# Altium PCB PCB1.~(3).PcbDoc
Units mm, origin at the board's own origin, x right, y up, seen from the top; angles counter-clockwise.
Board outline 127 x 101.6 mm, 3 copper layers (Top Layer, Internal Plane 1, Bottom Layer); 15 components, 13 nets, 51 pads, 0 vias.
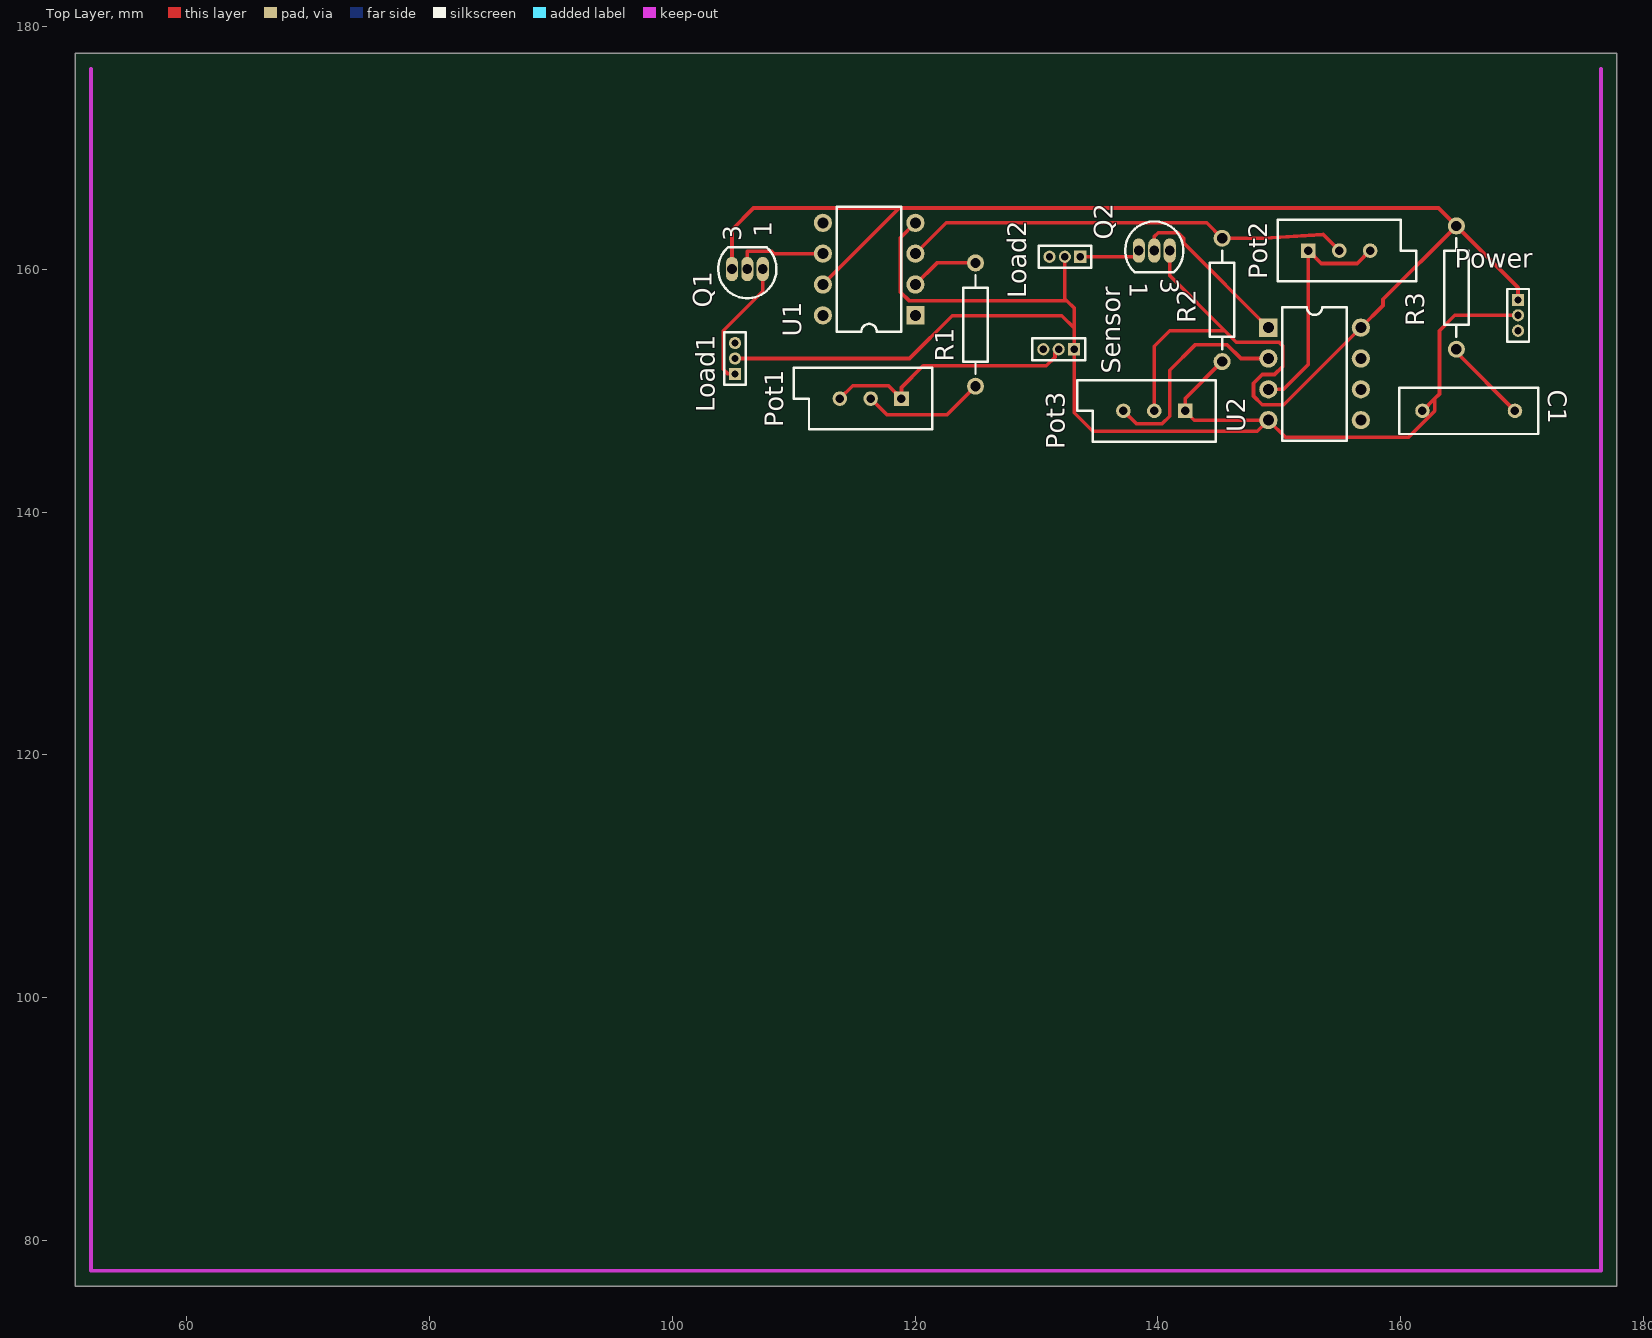
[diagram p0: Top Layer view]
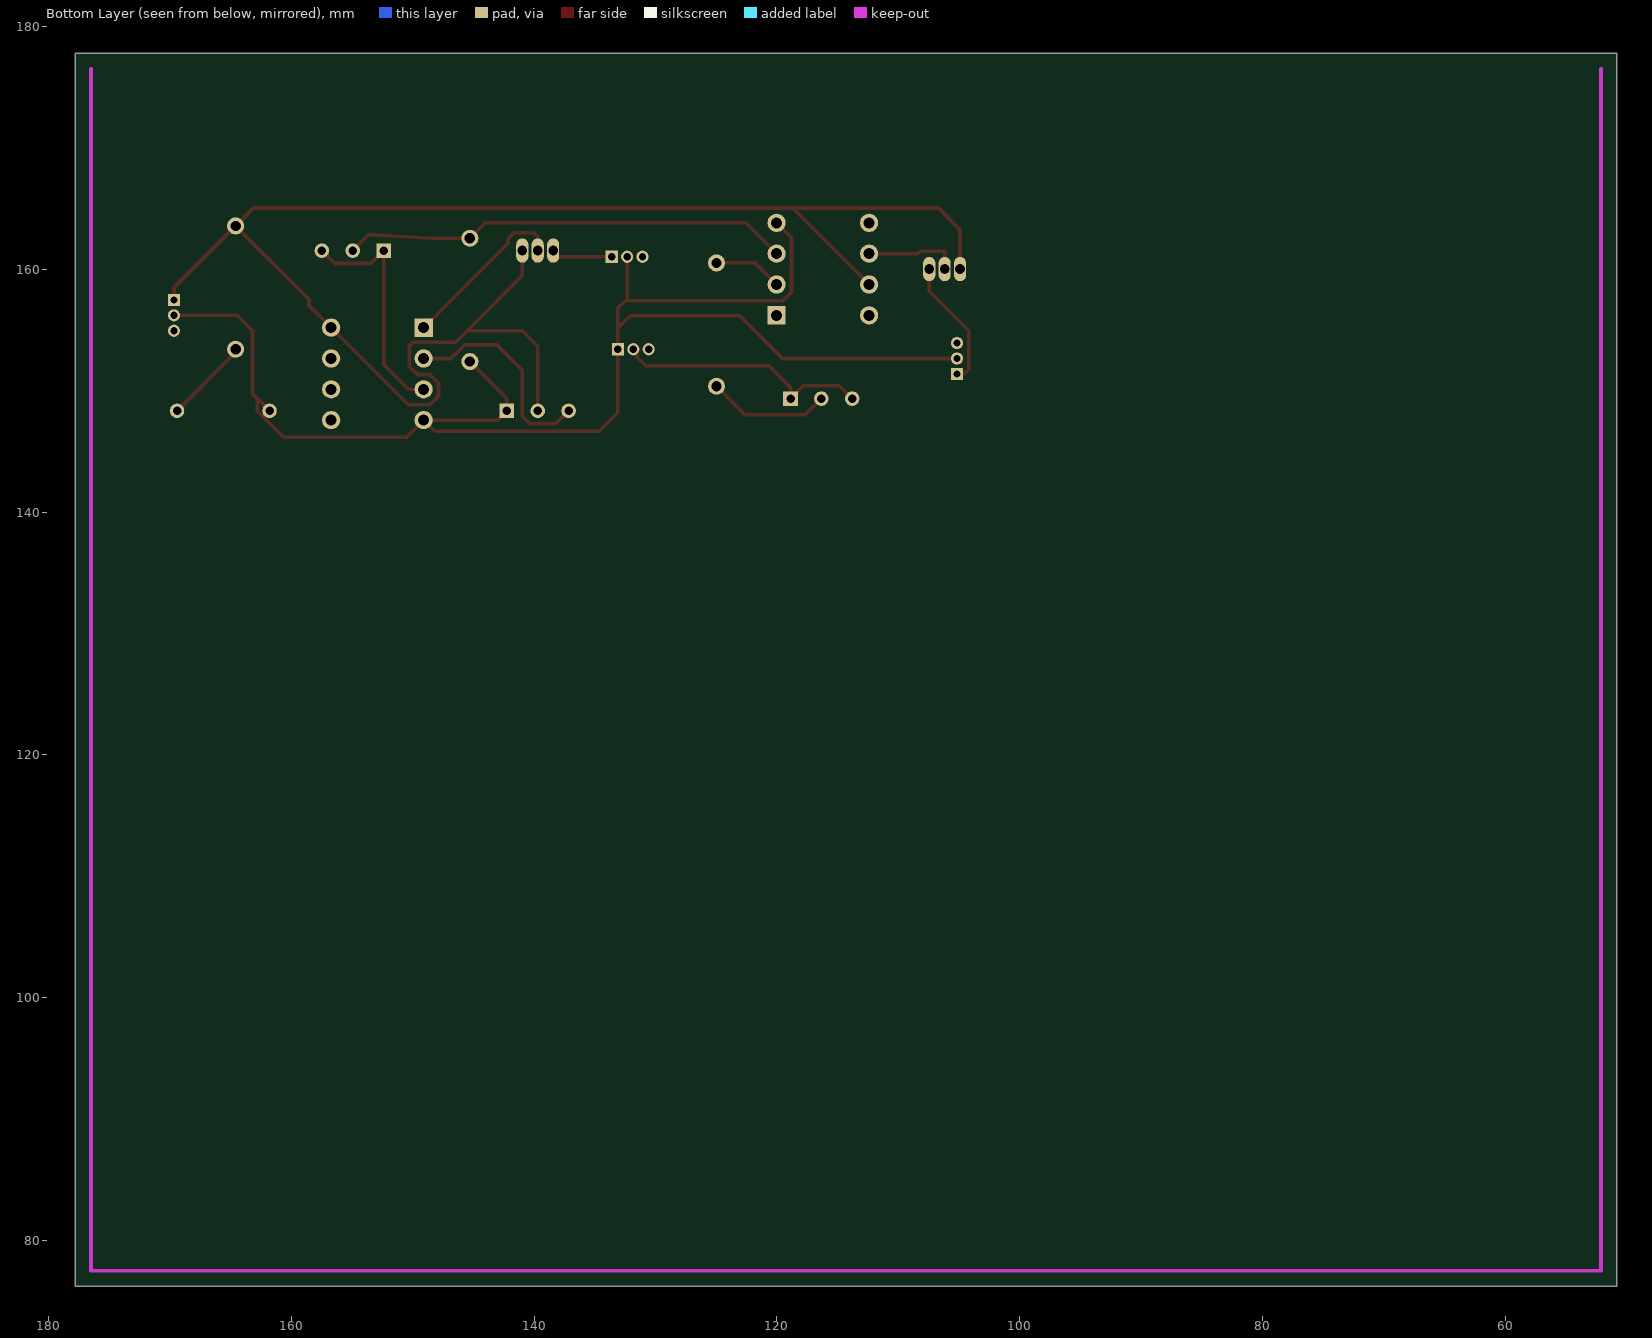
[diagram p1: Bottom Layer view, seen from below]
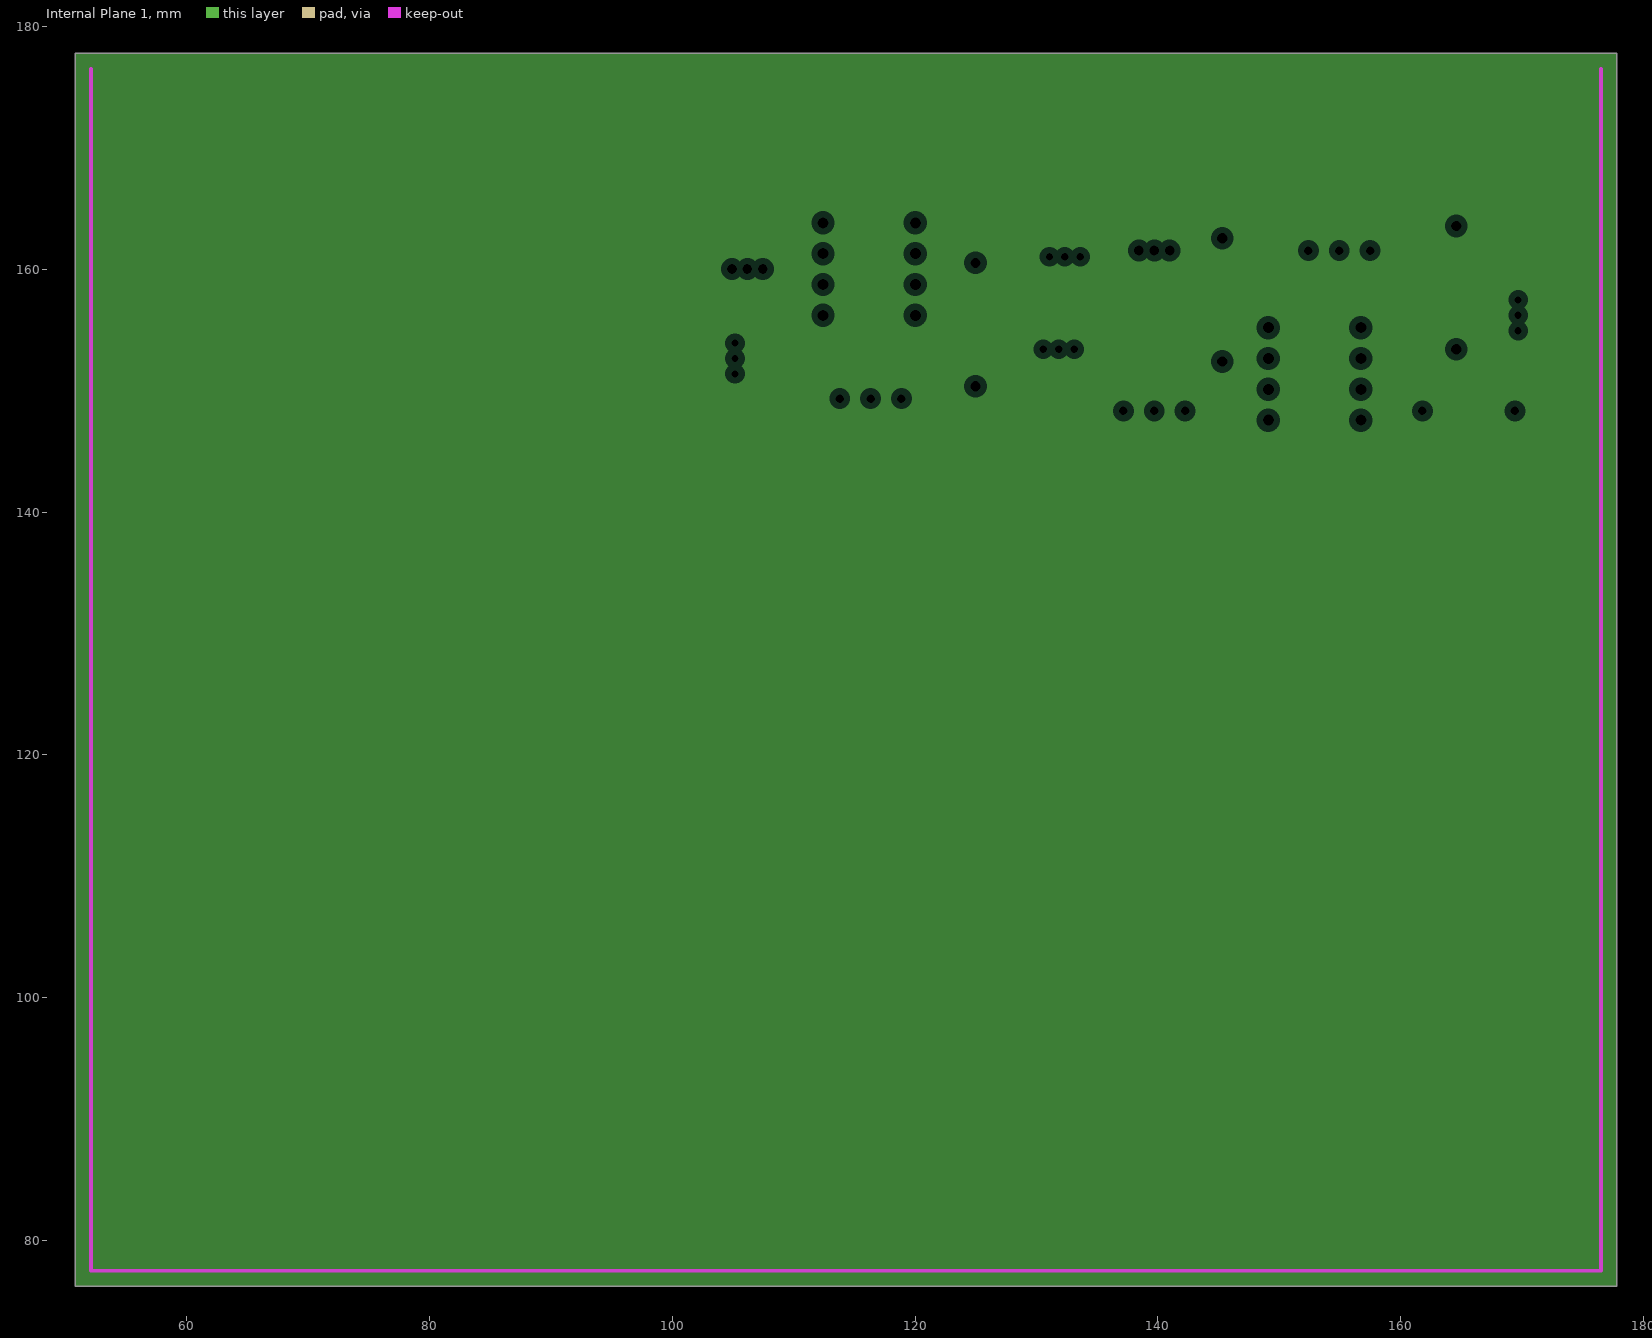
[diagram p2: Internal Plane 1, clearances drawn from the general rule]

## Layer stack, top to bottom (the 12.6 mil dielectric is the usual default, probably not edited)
Top Layer: signal copper 0.0356
Dielectric: dielectric 0.32, FR-4, Dk 4.8
Internal Plane 1: plane copper 0.0356
Dielectric: dielectric 0.32, FR-4, Dk 4.8
Bottom Layer: signal copper 0.0356

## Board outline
50.8,76.2 177.8,76.2 177.8,177.8 50.8,177.8

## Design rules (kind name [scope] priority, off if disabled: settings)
Clearance [All] p1: gap=0.3
ComponentClearance [All] p1: gap=0.254 collisioncheckmode=3 verticalgap=0.254
PlaneClearance [All] p1: clearance=0.508
PlaneConnect [All] p1: planeconnectstyle=Relief reliefexpansion=0.508 reliefentries=4 reliefconductorwidth=0.254 reliefairgap=0.254
PolygonConnect [All] p1: connectstyle=Relief reliefconductorwidth=0.254 reliefentries=4 polygonreliefangle="90 Angle"
RoomDefinition Sheet1 [InComponentClass('Sheet1')] p1: confinementstyle=ConfineIn formatcopy=TRUE lockcomponents=FALSE outline 0,0 50.8,0 50.8,25.4 0,25.4
RoutingVias [All] p1: holewidth=0.8 width=1.6 viastyle="Through Hole" minholewidth=0.711 minwidth=1.27 maxholewidth=0.711 maxwidth=1.27
SolderMaskExpansion [All] p1: expansion=0.102
TestPointUsage [All] p1: valid=0 allowmultiple=FALSE
Testpoint [All] p1: side=15 testpointundercomponent=TRUE minsize=1.016 maxsize=2.54 preferedsize=1.524 minholesize=0 maxholesize=1.016 preferedholesize=0.813 testpointgrid=0.025 style=1023 order=0-112345678
Width [All] p1: maxlimit=0.3 minlimit=0.3 preferedwidth=0.3
16 further rules are at their usual default settings.

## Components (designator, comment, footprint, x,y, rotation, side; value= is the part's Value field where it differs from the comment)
C1 "Cap" RAD-0.3 165.608,148.336 r0 top
Load1 "MHDR1X3" MHDR1X3 105.156,151.384 r90 top
Load2 "MHDR1X3" MHDR1X3 133.604,161.036 r180 top
Pot1 "RPot" VR5 116.332,149.352 r180 top
Pot2 "RPot" VR5 154.94,161.544 r0 top
Pot3 "RPot" VR5 139.7,148.336 r180 top
Power "MHDR1X3" MHDR1X3 169.672,157.48 r270 top
Q1 "BC547A" SOT54 106.172,160.02 r90 top
Q2 "BC547A" SOT54 139.7,161.544 r270 top
R1 "Res2" AXIAL-0.4 124.968,155.448 r90 top
R2 "Res2" AXIAL-0.4 145.288,157.48 r90 top
R3 "Res2" AXIAL-0.4 164.592,158.496 r90 top
Sensor "MHDR1X3" MHDR1X3 133.096,153.416 r180 top
U1 "LM741J/883" N08E 116.205,160.02 r90 top
U2 "LM393P" P008 152.908,151.384 r270 top

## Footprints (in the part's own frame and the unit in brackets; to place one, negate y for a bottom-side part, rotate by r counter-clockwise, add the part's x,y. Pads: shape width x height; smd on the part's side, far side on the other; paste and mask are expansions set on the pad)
AXIAL-0.4 [mm] "Resistor; 2 Leads"
  round 1.4 hole 0.85: 1(-5.08,0) 2(5.08,0)
  silkscreen extent -4.06,-1.02 4.06,1.02
MHDR1X3 [mm] "Connector; Header; 3 Position"
  rect 1x1 hole 0.6: 1(0,0)
  round 1 hole 0.6: 2(1.27,0) 3(2.54,0)
  silkscreen extent -0.9,-0.9 3.44,0.9
N08E [mm] "DIP; 8 Leads; Row Spacing 7.62 mm; Pitch 2.54 mm"
  rect 1.5x1.5 hole 0.9: 1(-3.81,-3.81)
  round 1.5 hole 0.9: 2(-1.27,-3.81) 3(1.27,-3.81) 4(3.81,-3.81) 5(3.81,3.81) 6(1.27,3.81) 7(-1.27,3.81) 8(-3.81,3.81)
  silkscreen extent -5.15,-2.65 5.15,2.65
P008 [mm] "DIP; 8 Leads; Row Spacing 7.62 mm; Pitch 2.54 mm"
  rect 1.5x1.5 hole 0.9: 1(-3.81,-3.81)
  round 1.5 hole 0.9: 2(-1.27,-3.81) 3(1.27,-3.81) 4(3.81,-3.81) 5(3.81,3.81) 6(1.27,3.81) 7(-1.27,3.81) 8(-3.81,3.81)
  silkscreen extent -5.5,-2.65 5.5,2.65
RAD-0.3 [mm] "Capacitor; 2 Leads"
  round 1.2 hole 0.7: 1(-3.81,0) 2(3.81,0)
  silkscreen extent -5.71,-1.91 5.71,1.91
SOT54 [mm] "TO, Flat Index; 3 In-Line, Axial Leads; Body Dia. 4.6mm; Leads 0.48 x 0.45 mm (max)"
  oval 2x1 hole 0.8: 1(0,-1.27) 2(0,0) 3(0,1.27)
  silkscreen extent -2.4,-2.4 1.8,2.4
VR5 [mm] "Potentiometer; 3 Leads"
  rect 1.2x1.2 hole 0.7: 1(-2.54,0)
  round 1.2 hole 0.7: 2(0,0) 3(2.54,0)
  silkscreen extent -5.08,-2.54 6.35,2.54

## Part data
C1: "Capacitor"
Load1 Load2 Power Sensor: "Header, 3-Pin"
Pot1 Pot2 Pot3: "Potentiometer"
Q1 Q2: "NPN General-purpose Transistor"
R1 R2 R3: "Resistor"
U1: "Operational Amplifier"
U2: "Dual Differential Comparator"

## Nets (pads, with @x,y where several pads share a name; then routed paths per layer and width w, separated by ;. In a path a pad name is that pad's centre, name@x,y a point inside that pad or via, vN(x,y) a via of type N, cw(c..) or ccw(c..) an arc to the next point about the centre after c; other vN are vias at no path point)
GND: C1.1 Load1.2 Load2.2 Pot3.1 Power.2 R2.1 Sensor.1 U1.4 U2.4 | length 123.1
  Top Layer w0.3: Load1.2 119.532,152.654 123.063,156.185 132.08,156.185 133.096,155.169 ; U1.4 118.796,162.611 118.796,158.115 119.482,157.429 132.499,157.416 ; Load2.2 132.334,157.582 132.499,157.416 ; R2.1 142.24,149.352 Pot3.1 143.002,147.574 U2.4 ; C1.1 162.814,149.352 ; Power.2 164.465,156.21 163.195,154.94 163.195,149.733 162.814,149.352 ; 132.499,157.416 133.096,156.82 133.096,155.169 ; 133.096,155.169 Sensor.1 133.096,148.184 134.62,146.66 148.184,146.66 U2.4 ; U2.4 150.52,146.152 160.63,146.152 162.306,147.828 162.814,148.336 162.814,149.352
NetC1_2: C1.2 R3.1 | length 7.1
  Top Layer w0.3: R3.1 164.592,153.162 C1.2
NetLoad1_1: Load1.1 Q1.1 | length 10.7
  Top Layer w0.3: Load1.1 104.572,151.384 104.191,151.765 104.191,154.94 107.442,158.191 Q1.1
NetLoad2_1: Load2.1 Q2.1 | length 5.3
  Top Layer w0.3: Load2.1 138.43,161.036 Q2.1
NetPot1_1: Pot1.1 Pot1.3 Sensor.2 | length 21.3
  Top Layer w0.3: Pot1.3 114.859,150.419 117.805,150.419 Pot1.1 118.872,150.266 120.65,152.044 130.81,152.044 131.521,152.756 131.521,153.111 Sensor.2
NetPot1_2: Pot1.2 R1.1 | length 10.2
  Top Layer w0.3: Pot1.2 117.653,148.031 122.631,148.031 R1.1
NetPot2_1: Pot2.1 Pot2.3 U2.3 | length 19.5
  Top Layer w0.3: U2.3 150.344,150.114 152.4,152.17 Pot2.1 153.467,160.477 156.413,160.477 Pot2.3
NetPot2_2: Pot2.2 R2.2 U1.3 | length 37.1
  Top Layer w0.3: U1.3 122.555,163.83 144.018,163.83 R2.2 148.692,162.56 153.619,162.865 Pot2.2
NetPot3_3: Pot3.3 U2.2 | length 17.8
  Top Layer w0.3: Pot3.3 138.227,147.269 140.335,147.269 140.97,147.904 140.97,151.689 143.053,153.772 145.72,153.772 146.838,152.654 U2.2
NetQ1_2: Q1.2 U1.6 | length 7.8
  Top Layer w0.3: Q1.2 106.172,161.493 108.179,161.493 108.382,161.29 U1.6
NetQ2_2: Q2.2 U2.1 | length 14.1
  Top Layer w0.3: Q2.2 139.7,162.7 140.017,163.017 141.656,163.017 142.113,162.56 142.113,162.179 U2.1
NetR1_2: R1.2 U1.2 | length 5.7
  Top Layer w0.3: U1.2 121.793,160.528 R1.2
VCC: Pot3.2 Power.1 Q1.3 Q2.3 R3.2 U1.7 U2.8 | length 136
  Top Layer w0.3: Q1.3 104.902,163.271 106.68,165.049 118.694,165.049 ; U1.7 118.694,165.049 ; Pot3.2 139.7,153.67 140.97,154.94 145.517,154.94 ; Q2.3 140.97,159.487 145.517,154.94 ; Power.1 169.672,158.496 R3.2 ; 118.694,165.049 163.119,165.049 R3.2 ; 145.517,154.94 146.463,153.994 149.974,153.994 150.298,153.67 150.298,152.025 149.606,151.333 148.59,151.333 147.879,150.622 147.879,149.555 148.59,148.844 150.368,148.844 U2.8 158.547,157.023 158.547,157.531 R3.2
pads on no net: Load1.3 Load2.3 Power.3 Sensor.3 U1.1 U1.5 U1.8 U2.5 U2.6 U2.7

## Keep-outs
Keep-Out Layer:
  lines w0.3: 52.1,176.5 52.1,77.5 176.5,77.5 176.5,176.5

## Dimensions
52.1,77.5 to 176.5,77.5 on Mechanical 1
52.1,77.5 to 52.1,176.5 on Mechanical 1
